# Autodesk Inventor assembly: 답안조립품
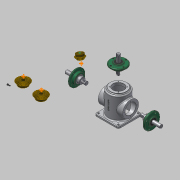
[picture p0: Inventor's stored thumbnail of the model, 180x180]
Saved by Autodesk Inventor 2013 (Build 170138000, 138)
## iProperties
Created: 2015-10
Part Number: 답안조립품
Document SubType Name: Assembly
Designer: Administrator
Author: Administrator
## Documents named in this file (14)
- C:\Users\Administrator\Desktop\451008V1002\답안조립품.iam
- C:\Users\Administrator\Desktop\451008V1002\본체.ipt
- C:\Users\Administrator\Desktop\451008V1002\M4.ipt
- C:\Users\Administrator\Desktop\451008V1002\메인 베벨기어.ipt
- C:\Users\Administrator\Desktop\451008V1002\메인 축.ipt
- 메인 축.ipt
- C:\Users\Administrator\Desktop\451008V1002\베어링 6203.ipt
- C:\Users\Administrator\Desktop\451008V1002\서브 베벨기어.ipt
- C:\Users\Administrator\Desktop\451008V1002\서브 축.ipt
- 서브 축.ipt
- C:\Users\Administrator\Desktop\451008V1002\오일실.ipt
- C:\Users\Administrator\Desktop\451008V1002\커버.ipt
- C:\Users\Administrator\Desktop\451008V1002\키 4x4.ipt
- C:\Users\Administrator\Desktop\451008V1002\키 5x5.ipt
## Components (1 placed, 1 different names)
1. M4:1
